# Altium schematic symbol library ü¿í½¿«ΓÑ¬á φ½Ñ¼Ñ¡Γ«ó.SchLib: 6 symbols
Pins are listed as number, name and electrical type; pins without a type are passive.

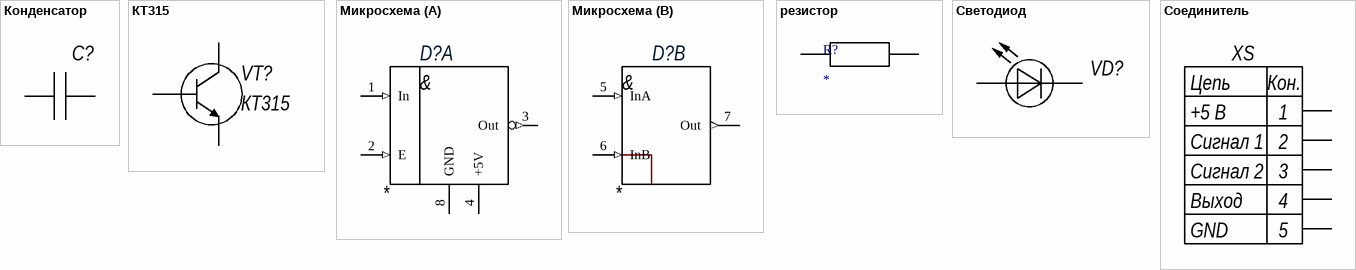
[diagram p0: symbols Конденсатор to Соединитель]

## Конденсатор
designator С?
footprint для электролитич.конденсатора
pins: 1, 2

## КТ315
designator VT?
footprint ПМ для кт 315
pins: B, C, E

## Микросхема
designator D?
footprint DIP8
part A pins: 1 In (in), 2 E (in), 3 Out (out), 4 +5V (power), 8 GND (power)
part B pins: 5 InA (in), 6 InB (in), 7 Out (out)

## резистор
designator R?
footprint ПМ для резистора
pins: 1, 2

## Светодиод
designator VD?
footprint для светоиода
pins: A, K

## Соединитель
designator ?  (value not drawn)
footprint для соединителя
pins: 1, 2, 3, 4, 5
